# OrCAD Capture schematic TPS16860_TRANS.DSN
size Custom; title: TPS54233 :2A, 28V INPUT, STEP DOWN SWIFT; rev: 1.0; note: SLVSHR6A
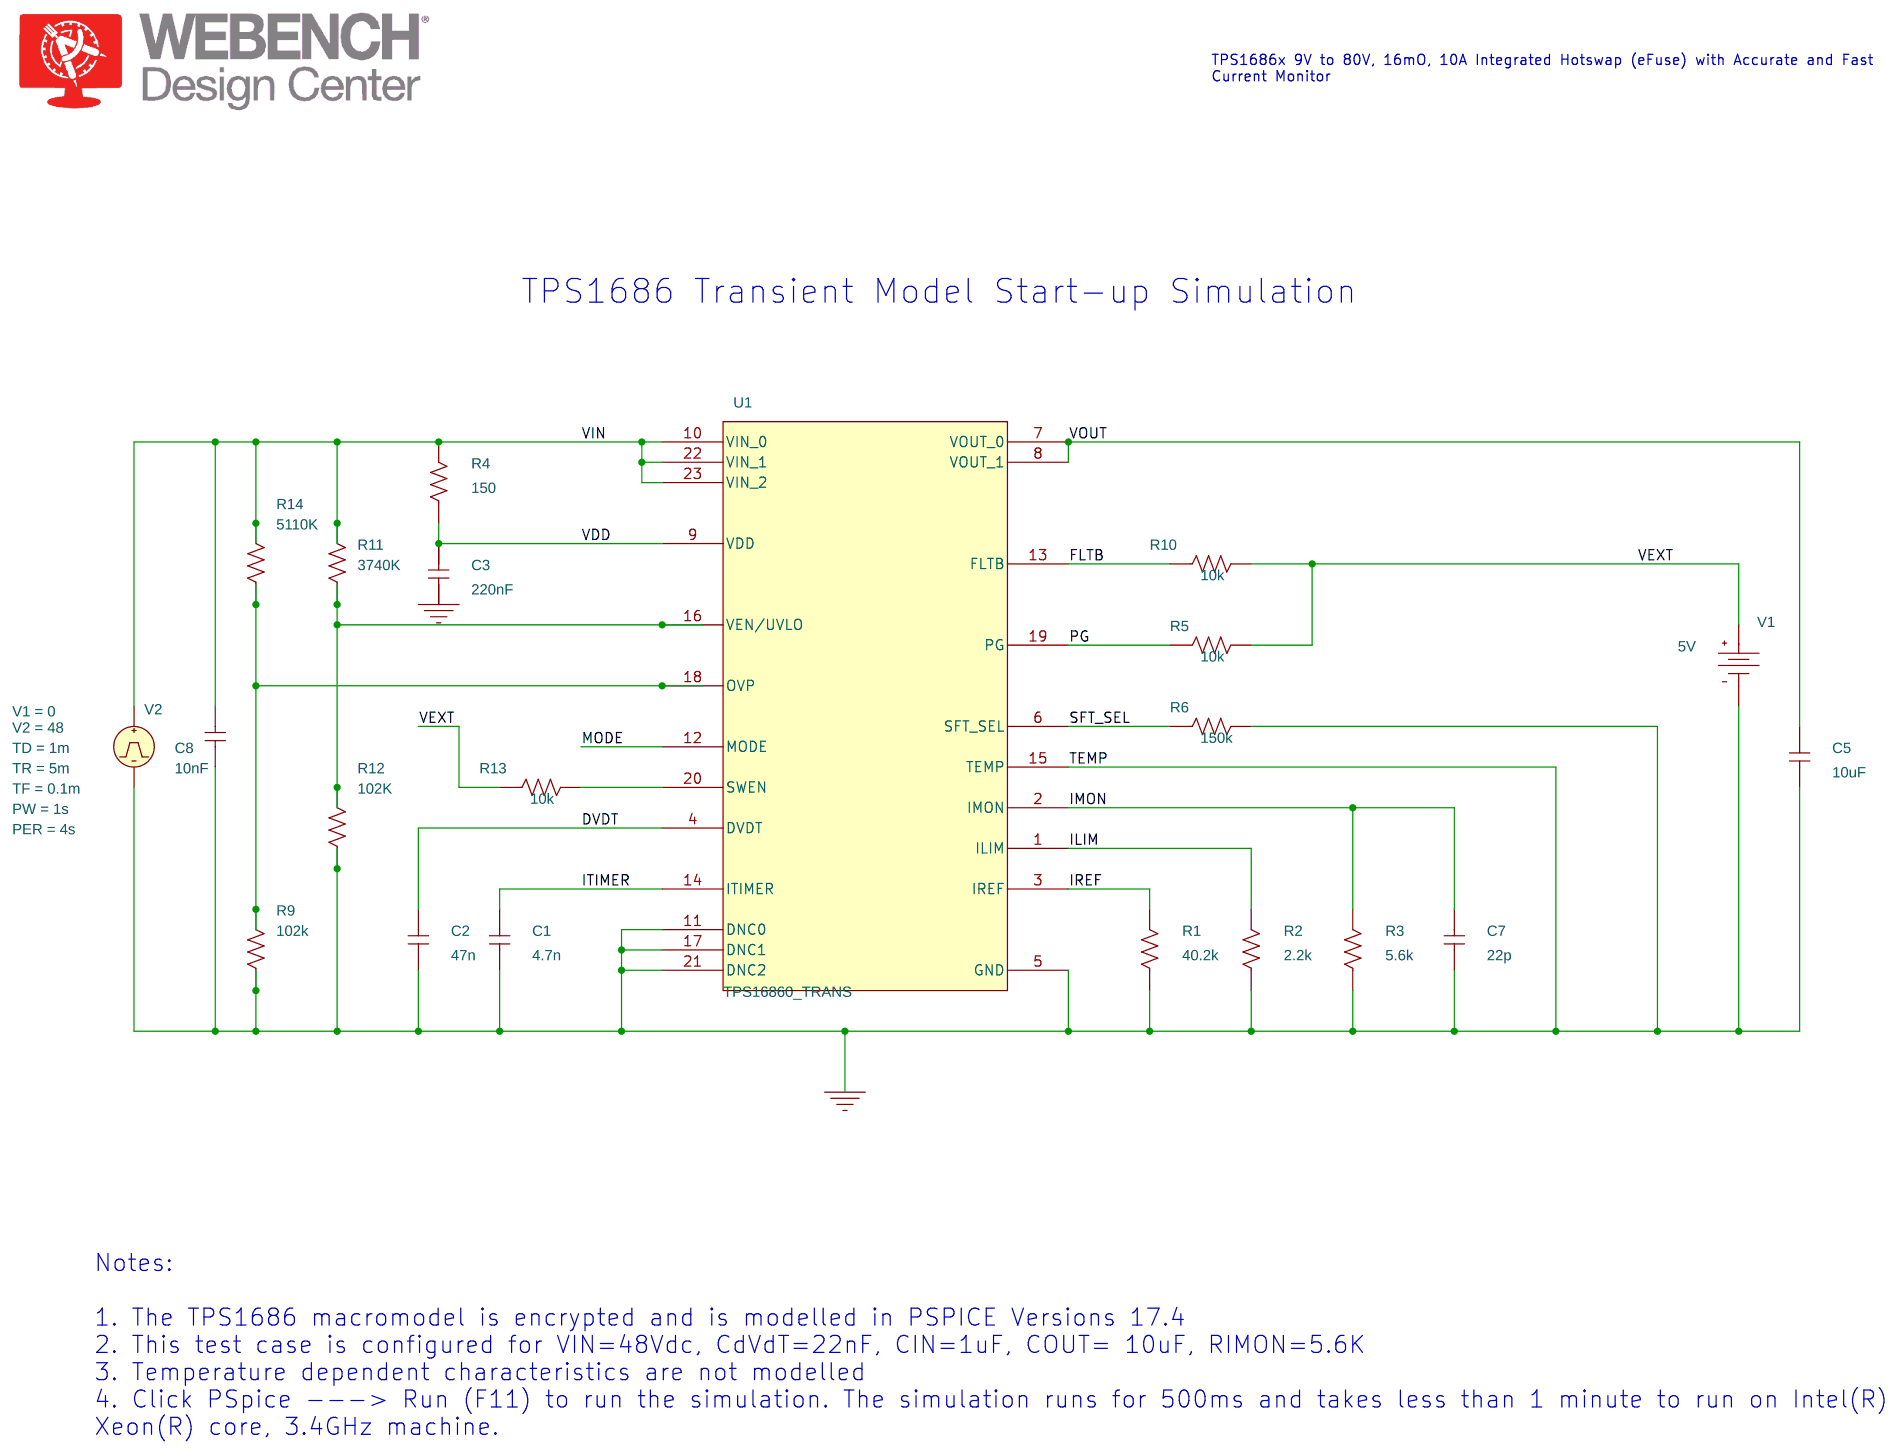
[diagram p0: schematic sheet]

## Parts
C1  4.7n  [cap196]
C2  47n  [cap196]
C3  220nF  [cap196]
C5  10uF  [cap196]
C7  22p  [cap196]
C8  10nF  [cap196]
R1  40.2k  [AXRC05]
R2  2.2k  [AXRC05]
R3  5.6k  [AXRC05]
R4  150  [AXRC05]
R5  10k  [AXRC05]
R6  150k  [AXRC05]
R9  102k  [AXRC05]
R10  10k  [AXRC05]
R11  3740K  [AXRC05]
R12  102K  [AXRC05]
R13  10k  [AXRC05]
R14  5110K  [AXRC05]
U1  TPS16860_TRANS
V1  VDC
V2  VPULSE

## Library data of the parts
C1-C3 C5 C7 C8 = C
R1-R6 R9-R14 = R
U1 = TPS1686_TRANS_2: PSpiceTemplate: X^@REFDES  %DNC0 %DNC1 %DNC2 %DVDT %FLTB %GND %ILIM %IMON %IREF %ITIMER %MODE %OVP %PG %SFT_SEL %SWEN %TEMP %VDD %VEN/UVLO %VIN_0 %VIN_1 %VIN_2 %VOUT_0 %VOUT_1 @MODEL
V1 = VDC: DC: 5V
V2 = VPULSE: PER: 4s; PW: 1s; TD: 1m; TF: 0.1m; TR: 5m; V1: 0; V2: 48

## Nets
VDD: C3.2 R4.1 U1.9(VDD)
VIN: C8.2 R4.2 R11.2 R14.2 U1.10(VIN_0) U1.22(VIN_1) U1.23(VIN_2) V2.1(+)
0: C1.1 C2.1 C3.1 C5.1 C7.1 C8.1 R1.1 R2.1 R3.1 R6.2 R9.1 R12.1 U1.5(GND) U1.11(DNC0) U1.15(TEMP) U1.17(DNC1) U1.21(DNC2) V1.1(-) V2.2(-)
DVDT: C2.2 U1.4(DVDT)
FLTB: R10.1 U1.13(FLTB)
ILIM: R2.2 U1.1(ILIM)
IMON: C7.2 R3.2 U1.2(IMON)
IREF: R1.2 U1.3(IREF)
ITIMER: C1.2 U1.14(ITIMER)
MODE: U1.12(MODE)
PG: R5.1 U1.19(PG)
SFT_SEL: R6.1 U1.6(SFT_SEL)
VEXT: R5.2 R10.2 R13.1 V1.0(+)
VOUT: C5.2 U1.7(VOUT_0) U1.8(VOUT_1)
N04607: R9.2 R14.1 U1.18(OVP)
N07243: R11.1 R12.2 U1.16(VEN/UVLO)
N09401: R13.2 U1.20(SWEN)

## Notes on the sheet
- TPS1686x 9V to 80V, 16mO, 10A Integrated Hotswap (eFuse) with Accurate and Fast
  Current Monitor
- TPS1686 Transient Model Start-up Simulation
- Notes:
  1. The TPS1686 macromodel is encrypted and is modelled in PSPICE Versions 17.4
  2. This test case is configured for VIN=48Vdc, CdVdT=22nF, CIN=1uF, COUT= 10uF, RIMON=5.6K
  3. Temperature dependent characteristics are not modelled
  4. Click PSpice ---> Run (F11) to run the simulation. The simulation runs for 500ms and takes less than 1 minute to run on Intel(R)
  Xeon(R) core, 3.4GHz machine.
